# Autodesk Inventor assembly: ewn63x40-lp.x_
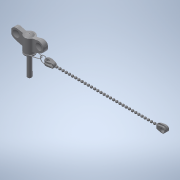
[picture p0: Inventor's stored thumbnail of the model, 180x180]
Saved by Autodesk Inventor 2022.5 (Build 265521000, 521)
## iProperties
Created: 2021-08
Part Number: ewn63x40-lp.x_
Material: 一般
Document SubType Name: Assembly
Designer: ImaoCorp
Sending System: SOLIDWORKS 2019-2019304
MC: AMD64
MC_MODEL: Intel64 Family 6 Model 60 Stepping 3, GenuineIntel
OS: Windows_NT
FRU: Parasolid Version 31.0, build 290,  9- 1-2019
FORMAT: text
GUISE: transmit
KEY: ewn63x40-lp
FILE: ewn63x40-lp.x_t
DATE: Wed Aug 11 15:05:04 2021
Author: ImaoCorp
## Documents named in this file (3)
- X:\14_SW2022-Inv2022\00_全2023-1023新製品(TCC)まで\e\ewn63x40-lp\EWN63X40-LP.iam
- X:\14_SW2022-Inv2022\00_全2023-1023新製品(TCC)まで\e\ewn63x40-lp\ewn63x40-lp_01.ipt
- X:\14_SW2022-Inv2022\00_全2023-1023新製品(TCC)まで\e\ewn63x40-lp\ewn63x40-lp_02.ipt
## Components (2 placed, 2 different names)
1. ewn63x40-lp_01
2. ewn63x40-lp_02
